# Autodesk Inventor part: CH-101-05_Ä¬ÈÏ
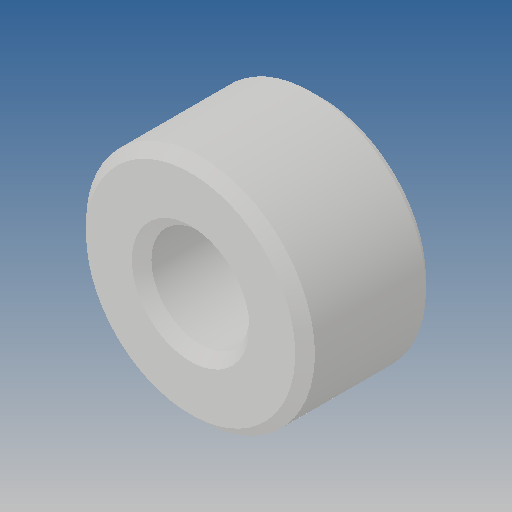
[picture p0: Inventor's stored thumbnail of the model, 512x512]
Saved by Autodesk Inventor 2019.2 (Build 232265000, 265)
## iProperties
Created: 2010-06
Part Number: CH-101-05_Ä¬ÈÏ
Material: Ogólny
Document SubType Name: Modeling
Designer: CADENGINEERING4
Density: 1 g/cm^3
Appearance: Domyślna
Author: CADENGINEERING4
Revision Number: ÈÎºÎ
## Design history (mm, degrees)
feature "NONE"
node "Bryła1"
